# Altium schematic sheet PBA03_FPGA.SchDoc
size D; DocumentNumber: 1; SheetNumber: 1; SheetTotal: 21; PageSetup: Record=PageOptions|CenterHorizontal=True|CenterVertical=True|PrintScale=0.50|XCorrection=1.00|YCorrection=1.00|PrintKind=2|BorderSize=5000000|LeftOffset=0|BottomOffset=0|Orientation=2|PaperLength=1000|PaperWidth=1000|Scale=100|PaperSource=7|PrintQuality=-4|MediaType=1|DitherType=10|PaperKind=A3 (297 x 420mm)|PrintScaleMode=1
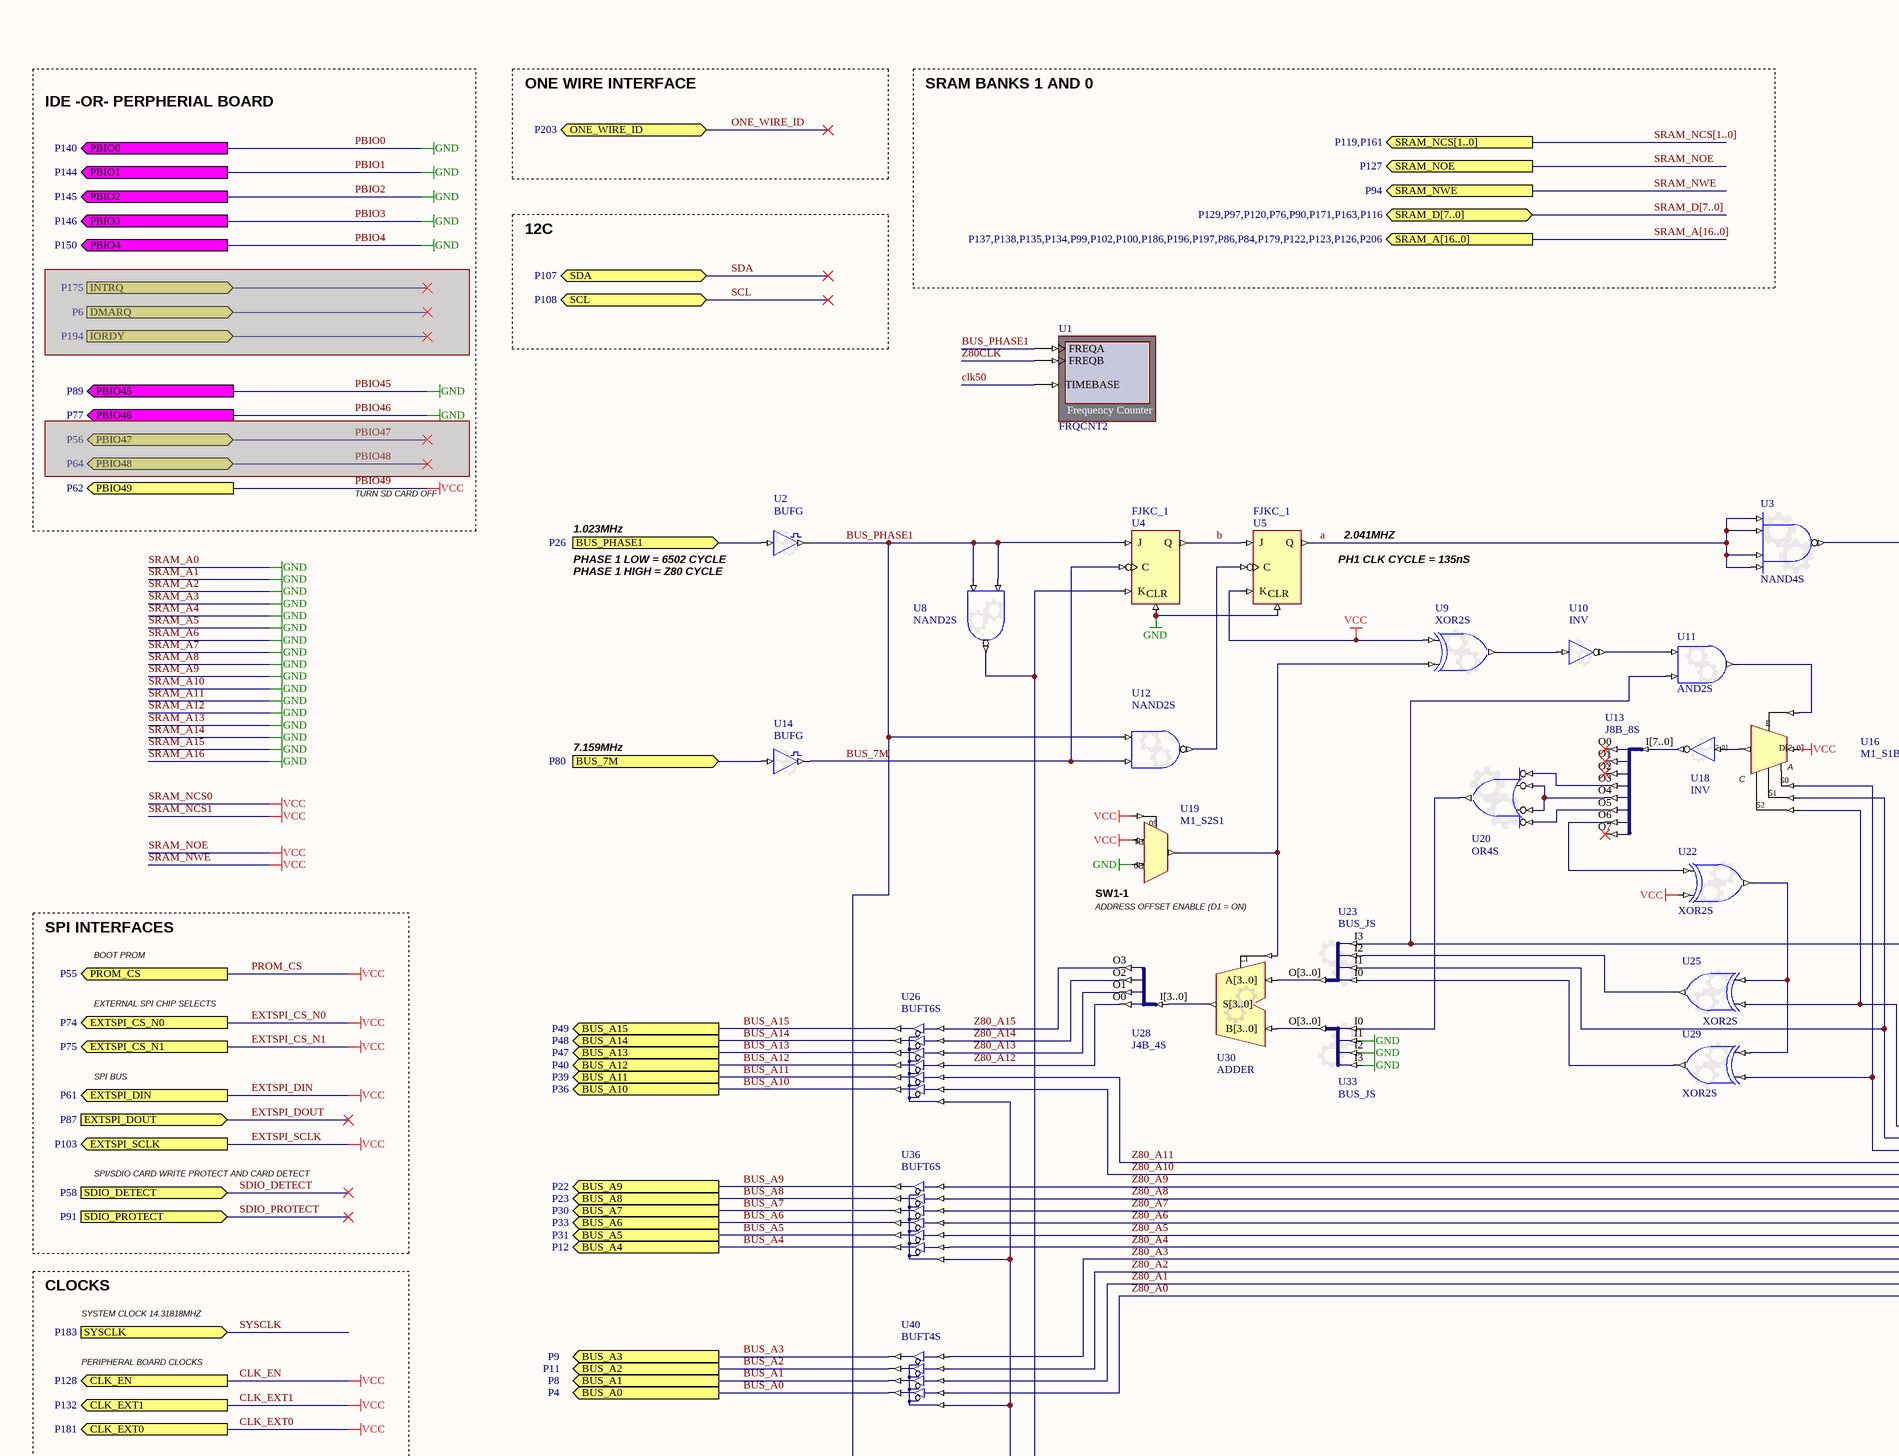
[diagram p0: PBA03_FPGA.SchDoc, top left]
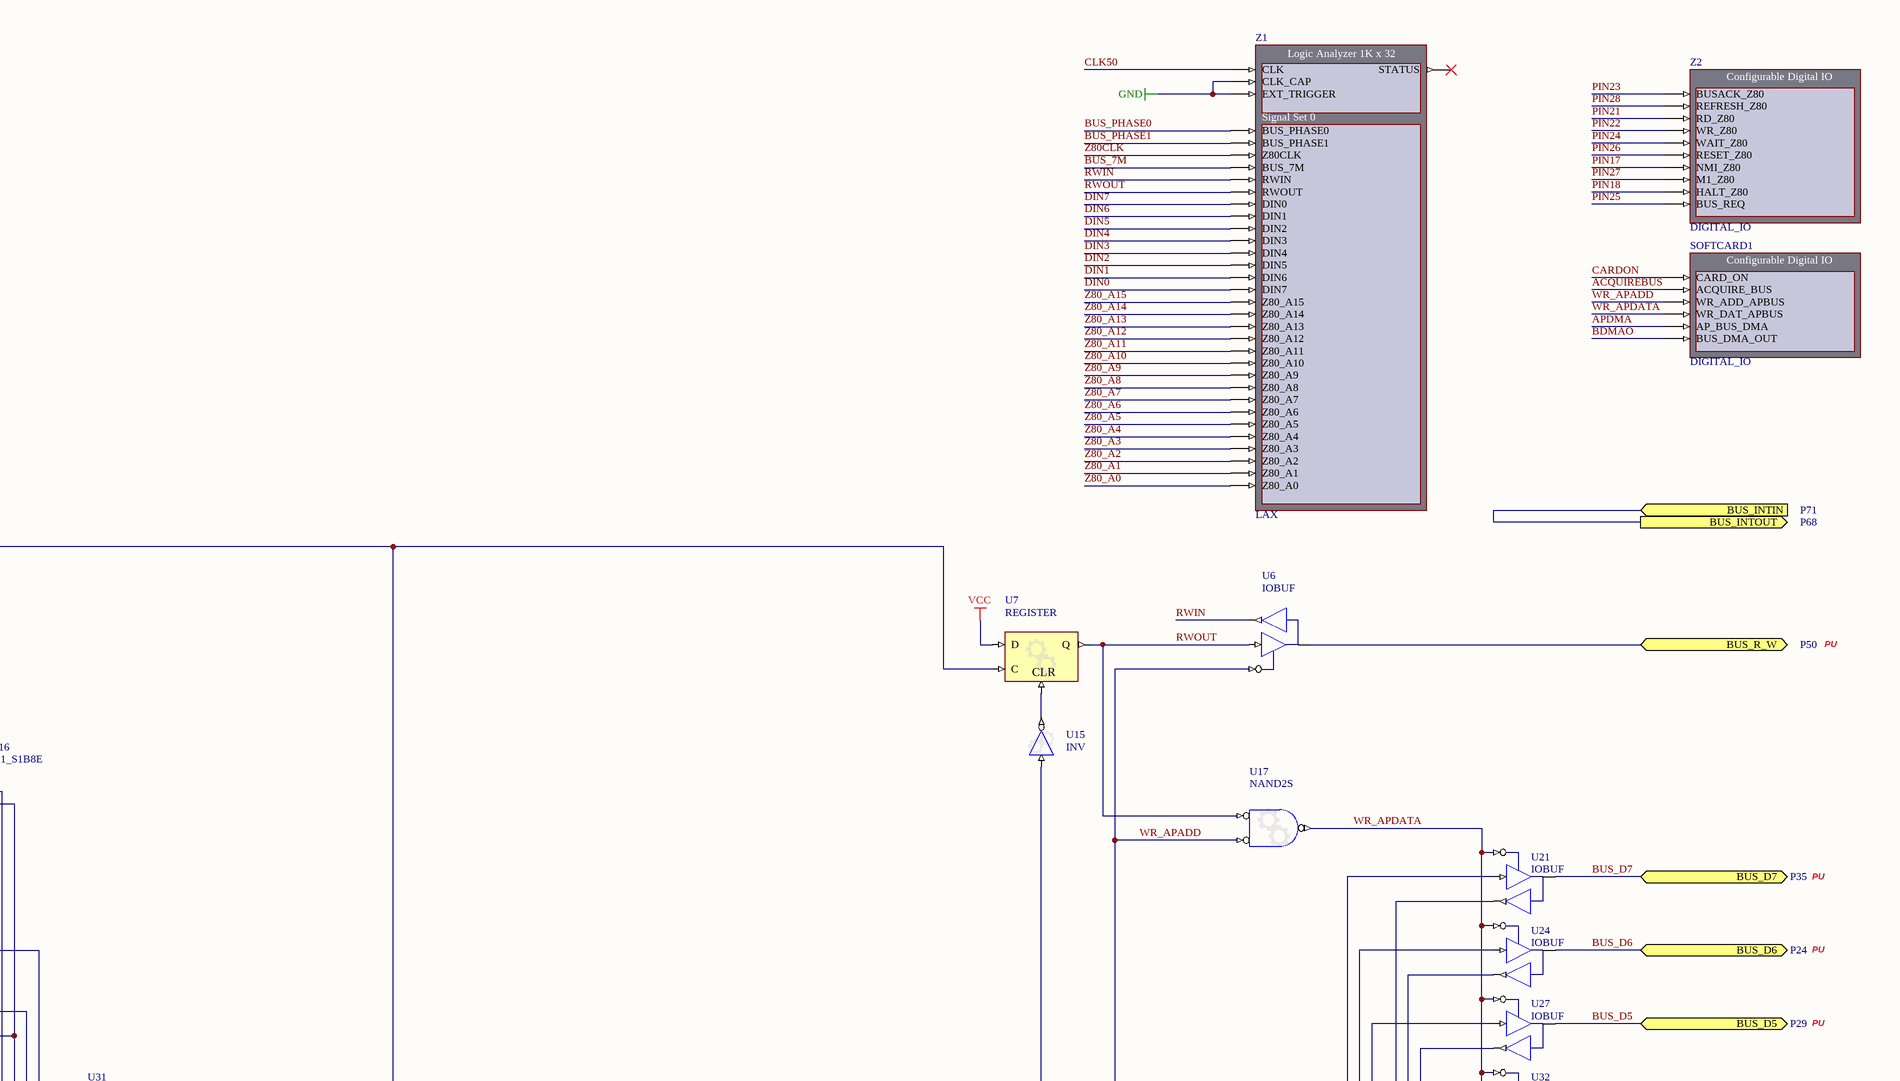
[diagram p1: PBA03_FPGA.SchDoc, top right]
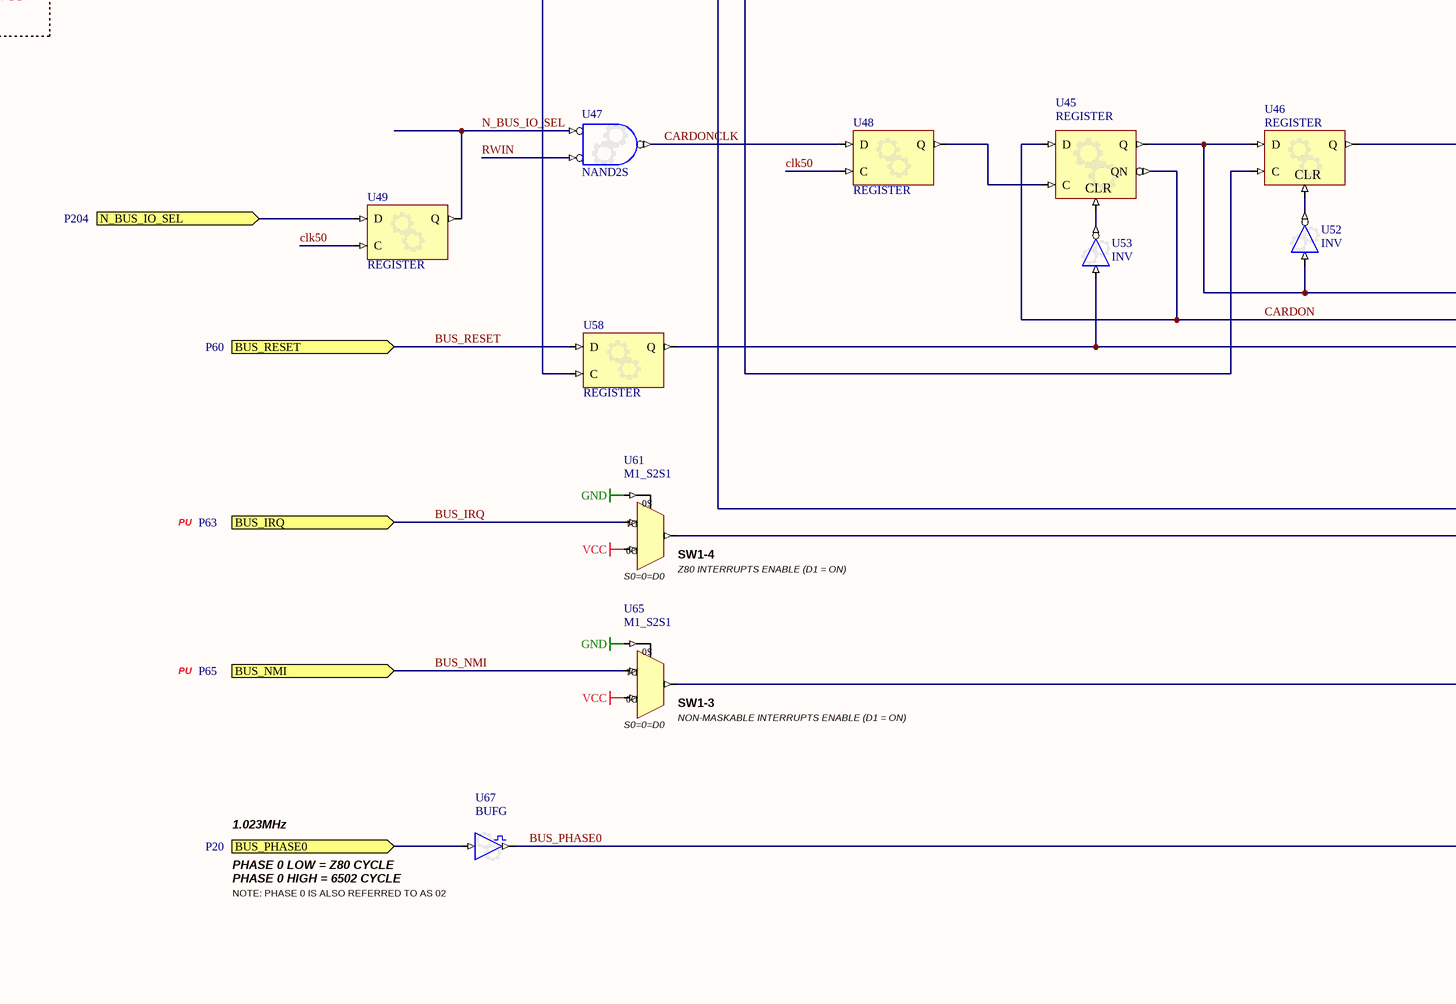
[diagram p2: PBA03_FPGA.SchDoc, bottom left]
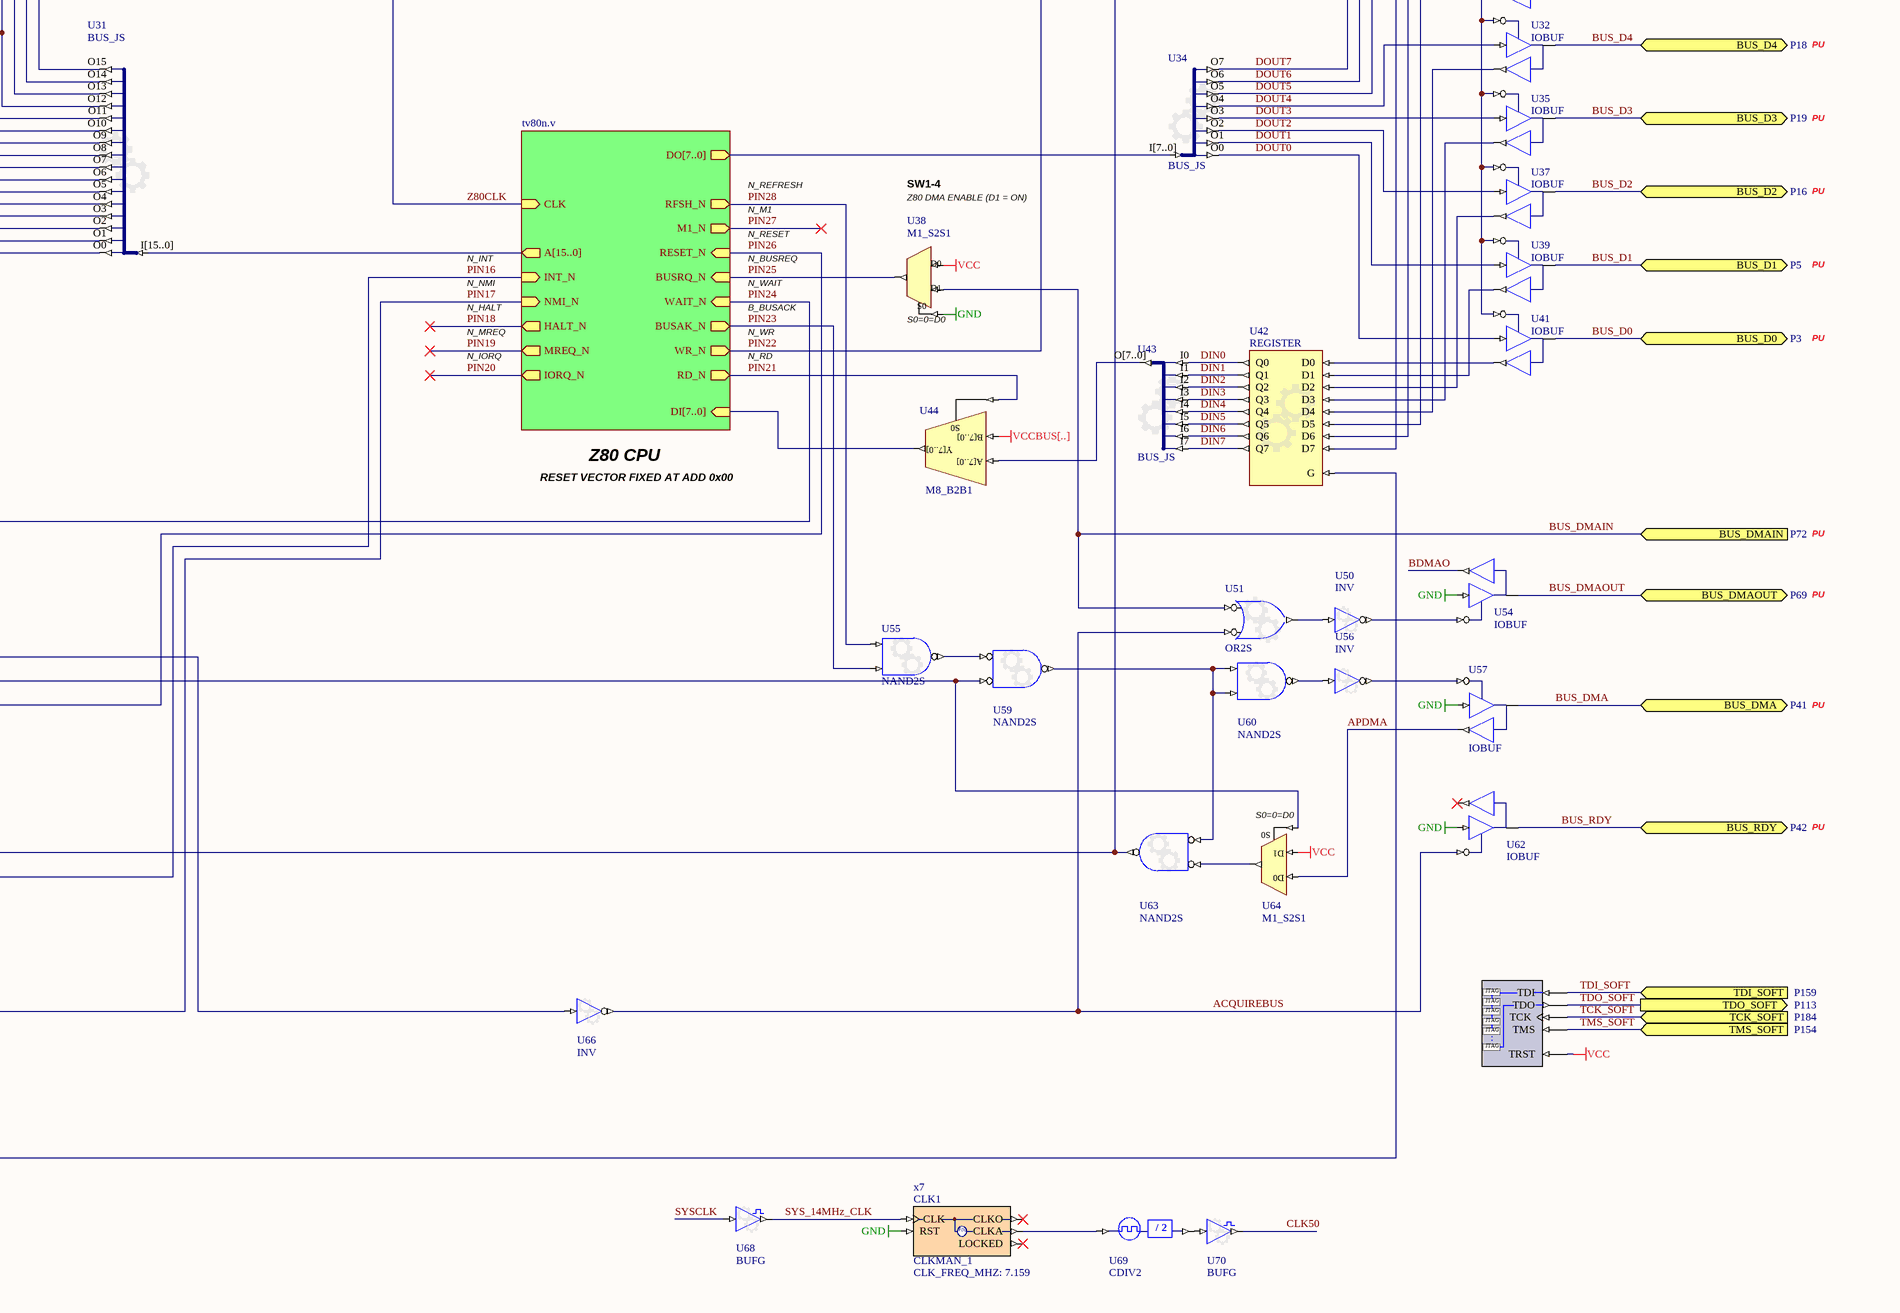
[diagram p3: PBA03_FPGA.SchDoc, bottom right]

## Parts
CLK1  CLKMAN_1  CLK_FREQ_MHZ: 7.159  ClkA_Operation: x7
NEXUS_JTAG_PORT  NEXUS_JTAG_PORT  (value not drawn)
SOFTCARD1  DIGITAL_IO
U1  FRQCNT2
U2  BUFG
U3  NAND4S
U4  FJKC_1
U5  FJKC_1
U6  IOBUF
U7  REGISTER
U8  NAND2S
U9  XOR2S
U10  INV
U11  AND2S
U12  NAND2S
U13  J8B_8S
U14  BUFG
U15  INV
U16  M1_S1B8E
U17  NAND2S
U18  INV
U19  M1_S2S1
U20  OR4S
U21  IOBUF
U22  XOR2S
U23  BUS_JS
U24  IOBUF
U25  XOR2S
U26  BUFT6S
U27  IOBUF
U28  J4B_4S
U29  XOR2S
U30  ADDER
U31  BUS_JS
U32  IOBUF
U33  BUS_JS
U34  BUS_JS
U35  IOBUF
U36  BUFT6S
U37  IOBUF
U38  M1_S2S1
U39  IOBUF
U40  BUFT4S
U41  IOBUF
U42  REGISTER
U43  BUS_JS
U44  M8_B2B1
U45  REGISTER
U46  REGISTER
U47  NAND2S
U48  REGISTER
U49  REGISTER
U50  INV
U51  OR2S
U52  INV
U53  INV
U54  IOBUF
U55  NAND2S
U56  INV
U57  IOBUF
U58  REGISTER
U59  NAND2S
U60  NAND2S
U61  M1_S2S1
U62  IOBUF
U63  NAND2S
U64  M1_S2S1
U65  M1_S2S1
U66  INV
U67  BUFG
U68  BUFG
U69  CDIV2
U70  BUFG
Z1  LAX
Z2  DIGITAL_IO

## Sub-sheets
U_Z80 = tv80n.v: A[15..0] (out), M1_N (out), IORQ_N (out), NMI_N (in), BUSRQ_N (in), RESET_N (in), WAIT_N (in), HALT_N (out), WR_N (out), RFSH_N (out), INT_N (in), BUSAK_N (out), MREQ_N (out), RD_N (out), DO[7..0] (out), DI[7..0] (in), CLK (in)  | : tv80n

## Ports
BUS_7M (in, see P80), BUS_A0 (out, see P4), BUS_A1 (out, see P8), BUS_A2 (out, see P11), BUS_A3 (out, see P9), BUS_A4 (out, see P12), BUS_A5 (out, see P31), BUS_A6 (out, see P33), BUS_A7 (out, see P30), BUS_A8 (out, see P23), BUS_A9 (out, see P22), BUS_A10 (out, see P36), BUS_A11 (out, see P39), BUS_A12 (out, see P40), BUS_A13 (out, see P47), BUS_A14 (out, see P48), BUS_A15 (out, see P49), BUS_D0 (bidir, see P3), BUS_D1 (bidir, see P5), BUS_D2 (bidir, see P16), BUS_D3 (bidir, see P19), BUS_D4 (bidir, see P18), BUS_D5 (bidir, see P29), BUS_D6 (bidir, see P24), BUS_D7 (bidir, see P35), BUS_DMA (bidir, see P41), BUS_DMAIN (in, see P72), BUS_DMAOUT (bidir, see P69), BUS_INTIN (in, see P71), BUS_INTOUT (out, see P68), BUS_IRQ (in, see P63), BUS_NMI (in, see P65), BUS_PHASE0 (in, see P20), BUS_PHASE1 (in, see P26), BUS_R_W (bidir, see P50), BUS_RDY (bidir, see P42), BUS_RESET (in, see P60), CLK_EN (out, see P128), CLK_EXT0 (out, see P181), CLK_EXT1 (out, see P132), DMARQ (in, see P6), EXTSPI_CS_N0 (out, see P74), EXTSPI_CS_N1 (out, see P75), EXTSPI_DIN (out, see P61), EXTSPI_DOUT (in, see P87), EXTSPI_SCLK (out, see P103), INTRQ (in, see P175), IORDY (in, see P194), N_BUS_IO_SEL (in, see P204), ONE_WIRE_ID (bidir, see P203), PBIO0 (out, see P140), PBIO1 (out, see P144), PBIO2 (out, see P145), PBIO3 (out, see P146), PBIO4 (out, see P150), PBIO45 (out, see P89), PBIO46 (out, see P77), PBIO47 (bidir, see P56), PBIO48 (bidir, see P64), PBIO49 (out, see P62), PROM_CS (out, see P55), SCL (bidir, see P108), SDA (bidir, see P107), SDIO_DETECT (in, see P58), SDIO_PROTECT (in, see P91), SRAM_A[16..0] (out, see P137,P138,P135,P134,P99,P102,P100,P186,P196,P197,P86,P84,P179,P122,P123,P126,P206), SRAM_D[7..0] (bidir, see P129,P97,P120,P76,P90,P171,P163,P116), SRAM_NCS[1..0] (out, see P119,P161), SRAM_NOE (out, see P127), SRAM_NWE (out, see P94), SYSCLK (in, see P183), TCK_SOFT (in, see P184), TDI_SOFT (in, see P159), TDO_SOFT (out, see P113), TMS_SOFT (in, see P154)

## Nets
CLK_EN: NEXUS_JTAG_PORT.TRST U5.K U7.D U9.I0 U16.O U19.D1 U19.S0 U22.I0 U38.D0 U61.D0 U64.D1 U65.D0 ; port PROM_CS, port EXTSPI_DIN, port EXTSPI_CS_N0, port EXTSPI_CS_N1, port SRAM_NWE, port EXTSPI_SCLK, port SRAM_NOE, port CLK_EN, port CLK_EXT1, port CLK_EXT0, port PBIO49  [also labelled CLK_EXT0, CLK_EXT1, EXTSPI_CS_N0, EXTSPI_CS_N1, EXTSPI_DIN, EXTSPI_SCLK, PBIO49, PROM_CS, SRAM_NCS0, SRAM_NCS1, SRAM_NOE, SRAM_NWE, VCC]
PBIO0: CLK1.RST U4.CLR U5.CLR U19.D0 U33.I1 U33.I2 U33.I3 U38.S0 U54.I U57.I U61.S0 U62.I U65.S0 Z1.CLK_CAP Z1.EXT_TRIGGER ; port PBIO0, port PBIO1, port PBIO2, port PBIO3, port PBIO4, port PBIO46, port PBIO45  [also labelled GND, PBIO1, PBIO2, PBIO3, PBIO4, PBIO45, PBIO46, SRAM_A0, SRAM_A1, SRAM_A10, SRAM_A11, SRAM_A12, SRAM_A13, SRAM_A14, SRAM_A15, SRAM_A16, SRAM_A2, SRAM_A3, SRAM_A4, SRAM_A5, SRAM_A6, SRAM_A7, SRAM_A8, SRAM_A9]
VCCBUS[..]: U44.B[7..0]
a: U3.I0 U3.I1 U3.I2 U3.I3 U5.Q
ACQUIREBUS: SOFTCARD1.ACQUIRE_BUS U51.I1 U62.T U66.O
APDMA: SOFTCARD1.AP_BUS_DMA U57.O U64.D0
b: U4.Q U5.J
BDMAO: SOFTCARD1.BUS_DMA_OUT U54.O
BUS_7M: U14.I ; port BUS_7M
BUS_7M: U4.C U12.I1 U14.O Z1.BUS_7M  [a separate net that carries the same name]
BUS_A0: U40.O0(Y0) ; port BUS_A0
BUS_A1: U40.O1(Y1) ; port BUS_A1
BUS_A2: U40.O2(Y2) ; port BUS_A2
BUS_A3: U40.O3(Y3) ; port BUS_A3
BUS_A4: U36.O0(Y0) ; port BUS_A4
BUS_A5: U36.O1(Y1) ; port BUS_A5
BUS_A6: U36.O2(Y2) ; port BUS_A6
BUS_A7: U36.O3(Y3) ; port BUS_A7
BUS_A8: U36.O4(Y4) ; port BUS_A8
BUS_A9: U36.O5(Y5) ; port BUS_A9
BUS_A10: U26.O0(Y0) ; port BUS_A10
BUS_A11: U26.O1(Y1) ; port BUS_A11
BUS_A12: U26.O2(Y2) ; port BUS_A12
BUS_A13: U26.O3(Y3) ; port BUS_A13
BUS_A14: U26.O4(Y4) ; port BUS_A14
BUS_A15: U26.O5(Y5) ; port BUS_A15
BUS_D0: U41.IO ; port BUS_D0
BUS_D1: U39.IO ; port BUS_D1
BUS_D2: U37.IO ; port BUS_D2
BUS_D3: U35.IO ; port BUS_D3
BUS_D4: U32.IO ; port BUS_D4
BUS_D5: U27.IO ; port BUS_D5
BUS_D6: U24.IO ; port BUS_D6
BUS_D7: U21.IO ; port BUS_D7
BUS_DMA: U57.IO ; port BUS_DMA
BUS_DMAIN: U38.D1 U51.I0 ; port BUS_DMAIN
BUS_DMAOUT: U54.IO ; port BUS_DMAOUT
BUS_INTIN: port BUS_INTIN, port BUS_INTOUT
BUS_IRQ: U61.D1 ; port BUS_IRQ
BUS_NMI: U65.D1 ; port BUS_NMI
BUS_PHASE0: U42.G U67.O Z1.BUS_PHASE0
BUS_PHASE0: U67.I ; port BUS_PHASE0  [a separate net that carries the same name]
BUS_PHASE1: U2.I ; port BUS_PHASE1
BUS_PHASE1: U1.FREQA U2.O U4.J U8.I0 U8.I1 U12.I0 U58.C Z1.BUS_PHASE1  [a separate net that carries the same name]
BUS_R_W: U6.IO ; port BUS_R_W
BUS_RDY: U62.IO ; port BUS_RDY
BUS_RESET: U58.D ; port BUS_RESET
CARDON: SOFTCARD1.CARD_ON U45.D U45.QN U59.I1 U64.S0
CARDONCLK: U47.O U48.D
CLK50: U1.TIMEBASE U48.C U49.C U70.O Z1.CLK
DIN0: U42.Q0 U43.I0 Z1.DIN7
DIN1: U42.Q1 U43.I1 Z1.DIN6
DIN2: U42.Q2 U43.I2 Z1.DIN5
DIN3: U42.Q3 U43.I3 Z1.DIN4
DIN4: U42.Q4 U43.I4 Z1.DIN3
DIN5: U42.Q5 U43.I5 Z1.DIN2
DIN6: U42.Q6 U43.I6 Z1.DIN1
DIN7: U42.Q7 U43.I7 Z1.DIN0
DOUT0: U34.O0 U41.I
DOUT1: U34.O1 U39.I
DOUT2: U34.O2 U37.I
DOUT3: U34.O3 U35.I
DOUT4: U32.I U34.O4
DOUT5: U27.I U34.O5
DOUT6: U24.I U34.O6
DOUT7: U21.I U34.O7
N_BUS_IO_SEL: U47.I1 U49.Q
N_BUS_IO_SEL: U49.D ; port N_BUS_IO_SEL  [a separate net that carries the same name]
PIN16: U61.O ; sheet U_Z80/INT_N
PIN17: U65.O Z2.NMI_Z80 ; sheet U_Z80/NMI_N
PIN18: Z2.HALT_Z80 ; sheet U_Z80/HALT_N
PIN21: U44.S0 Z2.RD_Z80 ; sheet U_Z80/RD_N
PIN22: U15.I Z2.WR_Z80 ; sheet U_Z80/WR_N
PIN23: U55.I1 Z2.BUSACK_Z80 ; sheet U_Z80/BUSAK_N
PIN24: U46.Q Z2.WAIT_Z80 ; sheet U_Z80/WAIT_N
PIN25: U38.O Z2.BUS_REQ ; sheet U_Z80/BUSRQ_N
PIN26: U53.I U58.Q Z2.RESET_Z80 ; sheet U_Z80/RESET_N
PIN27: Z2.M1_Z80 ; sheet U_Z80/M1_N
PIN28: U55.I0 Z2.REFRESH_Z80 ; sheet U_Z80/RFSH_N
RWIN: U6.O U47.I0 Z1.RWIN
RWOUT: U6.I U7.Q U17.I0 Z1.RWOUT
SYS_14MHz_CLK: CLK1.CLK U68.O
SYSCLK: U68.I ; port SYSCLK
TCK_SOFT: NEXUS_JTAG_PORT.TCK ; port TCK_SOFT
TDI_SOFT: NEXUS_JTAG_PORT.TDI ; port TDI_SOFT
TDO_SOFT: NEXUS_JTAG_PORT.TDO ; port TDO_SOFT
TMS_SOFT: NEXUS_JTAG_PORT.TMS ; port TMS_SOFT
WR_APADD: SOFTCARD1.WR_ADD_APBUS U6.T U17.I1 U26.T U36.T U40.T U63.O
WR_APDATA: SOFTCARD1.WR_DAT_APBUS U17.O U21.T U24.T U27.T U32.T U35.T U37.T U39.T U41.T
Z80_A0: U31.O0 U40.I0 Z1.Z80_A0
Z80_A1: U31.O1 U40.I1 Z1.Z80_A1
Z80_A2: U31.O2 U40.I2 Z1.Z80_A2
Z80_A3: U31.O3 U40.I3 Z1.Z80_A3
Z80_A4: U31.O4 U36.I0 Z1.Z80_A4
Z80_A5: U31.O5 U36.I1 Z1.Z80_A5
Z80_A6: U31.O6 U36.I2 Z1.Z80_A6
Z80_A7: U31.O7 U36.I3 Z1.Z80_A7
Z80_A8: U31.O8 U36.I4 Z1.Z80_A8
Z80_A9: U31.O9 U36.I5 Z1.Z80_A9
Z80_A10: U26.I0 U31.O10 Z1.Z80_A10
Z80_A11: U26.I1 U31.O11 Z1.Z80_A11
Z80_A12: U26.I2 U28.O0 Z1.Z80_A12
Z80_A13: U26.I3 U28.O1 Z1.Z80_A13
Z80_A14: U26.I4 U28.O2 Z1.Z80_A14
Z80_A15: U26.I5 U28.O3 Z1.Z80_A15
Z80CLK: U1.FREQB U3.O U7.C Z1.Z80CLK ; sheet U_Z80/CLK
NetCLK1_CLKA: CLK1.CLKA U69.CLKIN
NetU4_K: U4.K U8.O U46.C
NetU5_C: U5.C U12.O
NetU7_CLR: U7.CLR U15.O
NetU9_I1: U9.I1 U19.O U30.CI
NetU9_O: U9.O U10.I
NetU10_O: U10.O U11.I0
NetU11_I1: U11.I1 U23.I3 U31.O15
NetU11_O: U11.O U16.E
NetU13_O3: U13.O3 U20.I3
NetU13_O4: U13.O4 U20.I1 U20.I2
NetU13_O5: U13.O5 U20.I0
NetU13_O6: U13.O6 U22.I1
NetU16_S0: U16.S0 U29.I1 U31.O12
NetU16_S1: U16.S1 U23.I1 U31.O13
NetU16_S2: U16.S2 U25.I1 U31.O14
NetU20_O: U20.O U33.I0
NetU21_O: U21.O U42.D7
NetU22_O: U22.O U25.I0 U29.I0
NetU23_I0: U23.I0 U29.O
NetU23_I2: U23.I2 U25.O
NetU24_O: U24.O U42.D6
NetU27_O: U27.O U42.D5
NetU32_O: U32.O U42.D4
NetU35_O: U35.O U42.D3
NetU37_O: U37.O U42.D2
NetU39_O: U39.O U42.D1
NetU41_O: U41.O U42.D0
NetU45_C: U45.C U48.Q
NetU45_CLR: U45.CLR U53.O
NetU45_Q: U45.Q U46.D U52.I U66.I
NetU46_CLR: U46.CLR U52.O
NetU50_I: U50.I U51.O
NetU50_O: U50.O U54.T
NetU55_O: U55.O U59.I0
NetU56_I: U56.I U60.O
NetU56_O: U56.O U57.T
NetU59_O: U59.O U60.I0 U60.I1 U63.I1
NetU63_I0: U63.I0 U64.O
NetU69_CLKDV: U69.CLKDV U70.I

Not connected (* = marked no-connect by the designer): CLK1 CLKO* LOCKED*; U13 I[7..0] O0* O1* O2* O7*; U16 D[7..0]; U18 I[7..0] O[7..0]; U23 O[3..0]; U28 I[3..0]; U30 A[3..0] B[3..0] S[3..0]; U31 I[15..0]; U33 O[3..0]; U34 I[7..0]; U43 O[7..0]; U44 A[7..0] Y[7..0]; U62 O*; Z1 STATUS*

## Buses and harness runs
bus SRAM_A[16..0] = port SRAM_A[16..0]
bus SRAM_D[7..0] = port SRAM_D[7..0]
bus SRAM_NCS[1..0] = port SRAM_NCS[1..0]

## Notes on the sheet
- ONE WIRE INTERFACE
- SRAM BANKS 1 AND 0
- IDE -OR- PERPHERIAL BOARD
- 12C
- TURN SD CARD OFF
- 1.023MHz
- PHASE 1 LOW = 6502 CYCLE
- PHASE 1 HIGH = Z80 CYCLE
- (near U5) PH1 CLK CYCLE = 135nS
- (near U5) 2.041MHZ
- PU
- 7.159MHz
- (near U16) C
- (near U16) A
- SPI INTERFACES
- (near U19) SW1-1
- ADDRESS OFFSET ENABLE (D1 = ON)
- BOOT PROM
- EXTERNAL SPI CHIP SELECTS
- SPI BUS
- SPI/SDIO CARD WRITE PROTECT AND CARD DETECT
- N_REFRESH
- SW1-4
- Z80 DMA ENABLE (D1 = ON)
- CLOCKS
- SYSTEM CLOCK 14.31818MHZ
- N_INT
- N_M1
- N_BUSREQ
- N_RESET
- PERIPHERAL BOARD CLOCKS
- N_NMI
- N_HALT
- B_BUSACK
- N_WAIT
- (near U38) S0=0=D0
- N_MREQ
- N_IORQ
- N_RD
- N_WR
- RESET VECTOR FIXED AT ADD 0x00
- Z80 CPU
- (near U64) S0=0=D0
- (near U61) S0=0=D0
- (near U61) SW1-4
- (near U61) Z80 INTERRUPTS ENABLE (D1 = ON)
- (near U65) S0=0=D0
- (near U65) SW1-3
- (near U65) NON-MASKABLE INTERRUPTS ENABLE (D1 = ON)
- PHASE 0 LOW = Z80 CYCLE
- PHASE 0 HIGH = 6502 CYCLE
- NOTE: PHASE 0 IS ALSO REFERRED TO AS 02

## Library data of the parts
CLK1 = CLKMAN_1: Single Operational Output Clock Manager; Clk_Count: 1
NEXUS_JTAG_PORT = NEXUS_JTAG_PORT: Soft Nexus-Chain Connector; NEXUS_JTAG_CONNECTOR: True
SOFTCARD1 = DIGITAL_IO: Configurable Digital IO; NEXUS_CORE: Instrument; NEXUS_JTAG_DEVICE: True; NEXUS_JTAG_ORDER: 0; ConfigurationParameters: {}Version[1.0]{}Input0Name[CARD_ON]{}Input0Width[1]{}Input0InitValue[0]{}Input0Kind[LEDs]{}Input0LEDStyle[Red]{}Input1Name[ACQUIRE_BUS]{}Input1Width[1]{}Input1InitValue[0]{}Input1Kind[LEDs]{}Input1LEDStyle[Red]{}Input2Name[WR_ADD_APBUS]{}Input2Width[1]{}Input2InitValue[0]{}Input2Kind[LEDs]{}Input2LEDStyle[Red]{}Input3Name[WR_DAT_APBUS]{}Input3Width[1]{}Input3InitValue[0]{}Input3Kind[LEDs]{}Input3LEDStyle[Red]{}Input4Name[AP_BUS_DMA]{}Input4Width[1]{}Input4InitValue[0]{}Input4Kind[LEDs]{}Input4LEDStyle[Red]{}Input5Name[BUS_DMA_OUT]{}Input5Width[1]{}Input5InitValue[0]{}Input5Kind[LEDs]{}Input5LEDStyle[Red]{}
U1 = FRQCNT2: Frequency Counter; NEXUS_CORE: Instrument; NEXUS_JTAG_DEVICE: True; NEXUS_JTAG_ORDER: 0
U2 U14 U67 U68 U70 = BUFG: Configurable Global Clock Buffer; ConfiguratorName: GENERIC_BUFFER; ConfigurationParameters: {}Version[1.1]{}SignalCount[1]{}SignalWidth0[1]{}OutputOption0[Global Clock]{}EnableMode[None]{}ShowPinNames[False]{}
U3 = GATE: Configurable Generic Gate; ConfiguratorName: GENERIC_GATE; ConfigurationParameters: {}Version[1.1]{}GateKind[NAND]{}BusInput[False]{}GateInputType[Bit]{}GateOutputOption[Normal]{}BusWidth[8]{}RegisterOutputs[False]{}NegativeClockEdge[False]{}InputCount[4]{}InputInvert0[False]{}InputInvert1[False]{}InputInvert2[False]{}InputInvert3[False]{}
U4 U5 = FJKC_1: J-K Negative Edge Flip-Flop with Asynchronous Clear; SubClass: JK; ClockTrigger: Falling; ArchiveName: GENERIC; VHDLIB_SIM: GENERIC_LIB
U6 U21 U24 U27 U32 U35 U37 U39 U41 U54 U57 U62 = IOBUF: Input/Output Buffer; Enable: Low; Control: Common Control T; ArchiveName: GENERIC; VHDLIB_SIM: GENERIC_LIB
U7 U46 = REGISTER: Configurable Register; ConfiguratorName: GENERIC_REGISTER; ConfigurationParameters: {}Version[1.1]{}RegisterType[DFlipFlop]{}NegativeTrigger[False]{}TriggerEnable[False]{}ResetMode[Asynchronous]{}SetMode[None]{}SignalCount[1]{}SignalWidth0[1]{}OutputOption0[Normal]{}
U8 U12 U55 U60 = GATE: Configurable Generic Gate; ConfiguratorName: GENERIC_GATE; ConfigurationParameters: {}Version[1.1]{}GateKind[NAND]{}BusInput[False]{}GateInputType[Bit]{}GateOutputOption[Normal]{}BusWidth[8]{}RegisterOutputs[False]{}NegativeClockEdge[False]{}InputCount[2]{}InputInvert0[False]{}InputInvert1[False]{}
U9 U22 U25 U29 = GATE: Configurable Generic Gate; ConfiguratorName: GENERIC_GATE; ConfigurationParameters: {}Version[1.1]{}GateKind[XOR]{}BusInput[False]{}GateInputType[Bit]{}GateOutputOption[Normal]{}BusWidth[8]{}RegisterOutputs[False]{}NegativeClockEdge[False]{}InputCount[2]{}InputInvert0[False]{}InputInvert1[False]{}
U10 U15 U50 U52 U53 U56 U66 = INV: Configurable Inverter; ConfiguratorName: GENERIC_BUFFER; ConfigurationParameters: {}Version[1.1]{}SignalCount[1]{}SignalWidth0[1]{}OutputOption0[Inverted]{}EnableMode[None]{}ShowPinNames[False]{}
U11 = GATE: Configurable Generic Gate; ConfiguratorName: GENERIC_GATE; ConfigurationParameters: {}Version[1.1]{}GateKind[AND]{}BusInput[False]{}GateInputType[Bit]{}GateOutputOption[Normal]{}BusWidth[8]{}RegisterOutputs[False]{}NegativeClockEdge[False]{}InputCount[2]{}InputInvert0[False]{}InputInvert1[False]{}
U13 = J8B_8S: 8-Bit input bus to 8 single pin outputs; FunctionalClass: Bus Joiner; PortSize: 8; ArchiveName: GENERIC; VHDLIB_SIM: GENERIC_LIB
U16 = M1_S1B8E: 1x1-Single Wire to 1x8-Bit Bus Multiplexer (Demultiplex) With Enable; SubClass: S1Bn; Enable: High; PortSize: 1; PortStyle: Bus Version; ArchiveName: GENERIC; VHDLIB_SIM: GENERIC_LIB
U17 U47 U59 U63 = GATE: Configurable Generic Gate; ConfiguratorName: GENERIC_GATE; ConfigurationParameters: {}Version[1.1]{}GateKind[NAND]{}BusInput[False]{}GateInputType[Bit]{}GateOutputOption[Normal]{}BusWidth[8]{}RegisterOutputs[False]{}NegativeClockEdge[False]{}InputCount[2]{}InputInvert0[True]{}InputInvert1[True]{}
U18 = INV: Configurable Inverter; ConfigurationParameters: {}Version[1.1]{}SignalCount[1]{}SignalWidth0[8]{}OutputOption0[Inverted]{}EnableMode[None]{}ShowPinNames[False]{}; ConfiguratorName: GENERIC_BUFFER
U19 U38 U61 U64 U65 = M1_S2S1: 2x1-Single Wire to 1x1-Single Wire Multiplexer; XilinxEquivalent: M2_1; SubClass: SnS1; PortSize: 1; PortStyle: Single Pin Version; ArchiveName: GENERIC; VHDLIB_SIM: GENERIC_LIB
U20 = GATE: Configurable Generic Gate; ConfiguratorName: GENERIC_GATE; ConfigurationParameters: {}Version[1.1]{}GateKind[OR]{}BusInput[False]{}GateInputType[Bit]{}GateOutputOption[Normal]{}BusWidth[8]{}RegisterOutputs[False]{}NegativeClockEdge[False]{}InputCount[4]{}InputInvert0[True]{}InputInvert1[True]{}InputInvert2[True]{}InputInvert3[True]{}
U23 U33 = BUS_JS: Configurable Bus Joiner/Splitter; ConfiguratorName: GENERIC_BUS_JS; ConfigurationParameters: {}Version[1.1]{}SplitterJoinerType[Joiner]{}SignalCount[4]{}SignalWidth0[1]{}GapBelow0[1000000]{}ConnectionType0[Pin]{}SignalWidth1[1]{}GapBelow1[1000000]{}ConnectionType1[Pin]{}SignalWidth2[1]{}GapBelow2[1000000]{}ConnectionType2[Pin]{}SignalWidth3[1]{}GapBelow3[1000000]{}ConnectionType3[Pin]{}ShowPinNames[True]{}
U26 U36 = BUFT6S: 6-Bit 3-state Buffer with Active Low Enable, Single Pin Version; SubClass: BUFT; PortSize: 6; ArchiveName: GENERIC; VHDLIB_SIM: GENERIC_LIB
U28 = J4B_4S: 4-Bit input bus to 4 Single pin outputs; FunctionalClass: Bus Joiner; PortSize: 4; ArchiveName: GENERIC; VHDLIB_SIM: GENERIC_LIB
U30 = ADDER: Configurable Adder; ConfiguratorName: GENERIC_ADDER; ConfigurationParameters: {}Version[1.0]{}Type[Adder]{}SignedOverflow[False]{}UnsignedCarryOut[False]{}SignalWidth[4]{}BusInputs[True]{}BusOutput[True]{}RegisterOutputs[False]{}NegClockEdge[False]{}CarryIn[True]{}
U31 = BUS_JS: Configurable Bus Joiner/Splitter; ConfiguratorName: GENERIC_BUS_JS; ConfigurationParameters: {}Version[1.1]{}SplitterJoinerType[Splitter]{}SignalCount[16]{}SignalWidth0[1]{}GapBelow0[1000000]{}ConnectionType0[Pin]{}SignalWidth1[1]{}GapBelow1[1000000]{}ConnectionType1[Pin]{}SignalWidth2[1]{}GapBelow2[1000000]{}ConnectionType2[Pin]{}SignalWidth3[1]{}GapBelow3[1000000]{}ConnectionType3[Pin]{}SignalWidth4[1]{}GapBelow4[1000000]{}ConnectionType4[Pin]{}SignalWidth5[1]{}GapBelow5[1000000]{}ConnectionType5[Pin]{}SignalWidth6[1]{}GapBelow6[1000000]{}ConnectionType6[Pin]{}SignalWidth7[1]{}GapBelow7[1000000]{}ConnectionType7[Pin]{}SignalWidth8[1]{}GapBelow8[1000000]{}ConnectionType8[Pin]{}SignalWidth9[1]{}GapBelow9[1000000]{}ConnectionType9[Pin]{}SignalWidth10[1]{}GapBelow10[1000000]{}ConnectionType10[Pin]{}SignalWidth11[1]{}GapBelow11[1000000]{}ConnectionType11[Pin]{}SignalWidth12[1]{}GapBelow12[1000000]{}ConnectionType12[Pin]{}SignalWidth13[1]{}GapBelow13[1000000]{}ConnectionType13[Pin]{}SignalWidth14[1]{}GapBelow14[1000000]{}ConnectionType14[Pin]{}SignalWidth15[1]{}GapBelow15[1000000]{}ConnectionType15[Pin]{}ShowPinNames[True]{}
U34 = BUS_JS: Configurable Bus Joiner/Splitter; ConfiguratorName: GENERIC_BUS_JS; ConfigurationParameters: {}Version[1.1]{}SplitterJoinerType[Splitter]{}SignalCount[8]{}SignalWidth0[1]{}GapBelow0[1000000]{}ConnectionType0[Pin]{}SignalWidth1[1]{}GapBelow1[1000000]{}ConnectionType1[Pin]{}SignalWidth2[1]{}GapBelow2[1000000]{}ConnectionType2[Pin]{}SignalWidth3[1]{}GapBelow3[1000000]{}ConnectionType3[Pin]{}SignalWidth4[1]{}GapBelow4[1000000]{}ConnectionType4[Pin]{}SignalWidth5[1]{}GapBelow5[1000000]{}ConnectionType5[Pin]{}SignalWidth6[1]{}GapBelow6[1000000]{}ConnectionType6[Pin]{}SignalWidth7[1]{}GapBelow7[1000000]{}ConnectionType7[Pin]{}ShowPinNames[True]{}
U40 = BUFT4S: 4-Bit 3-state Buffer with Active Low Enable, Single Pin Version; XilinxEquivalent: BUFT4; SubClass: BUFT; PortSize: 4; ArchiveName: GENERIC; VHDLIB_SIM: GENERIC_LIB
U42 = REGISTER: Configurable Register; ConfiguratorName: GENERIC_REGISTER; ConfigurationParameters: {}Version[1.1]{}RegisterType[TransparentLatch]{}NegativeTrigger[False]{}TriggerEnable[False]{}ResetMode[None]{}SetMode[None]{}SignalCount[8]{}SignalWidth0[1]{}OutputOption0[Normal]{}SignalWidth1[1]{}OutputOption1[Normal]{}SignalWidth2[1]{}OutputOption2[Normal]{}SignalWidth3[1]{}OutputOption3[Normal]{}SignalWidth4[1]{}OutputOption4[Normal]{}SignalWidth5[1]{}OutputOption5[Normal]{}SignalWidth6[1]{}OutputOption6[Normal]{}SignalWidth7[1]{}OutputOption7[Normal]{}
U43 = BUS_JS: Configurable Bus Joiner/Splitter; ConfiguratorName: GENERIC_BUS_JS; ConfigurationParameters: {}Version[1.1]{}SplitterJoinerType[Joiner]{}SignalCount[8]{}SignalWidth0[1]{}GapBelow0[1000000]{}ConnectionType0[Pin]{}SignalWidth1[1]{}GapBelow1[1000000]{}ConnectionType1[Pin]{}SignalWidth2[1]{}GapBelow2[1000000]{}ConnectionType2[Pin]{}SignalWidth3[1]{}GapBelow3[1000000]{}ConnectionType3[Pin]{}SignalWidth4[1]{}GapBelow4[1000000]{}ConnectionType4[Pin]{}SignalWidth5[1]{}GapBelow5[1000000]{}ConnectionType5[Pin]{}SignalWidth6[1]{}GapBelow6[1000000]{}ConnectionType6[Pin]{}SignalWidth7[1]{}GapBelow7[1000000]{}ConnectionType7[Pin]{}ShowPinNames[True]{}
U44 = M8_B2B1: 2x8-Bit Bus to 1x8-Bit Bus Multiplexer; SubClass: BnB1; PortSize: 8; PortStyle: Bus Version; ArchiveName: GENERIC; VHDLIB_SIM: GENERIC_LIB
U45 = REGISTER: Configurable Register; ConfiguratorName: GENERIC_REGISTER; ConfigurationParameters: {}Version[1.1]{}RegisterType[DFlipFlop]{}NegativeTrigger[False]{}TriggerEnable[False]{}ResetMode[Asynchronous]{}SetMode[None]{}SignalCount[1]{}SignalWidth0[1]{}OutputOption0[Both]{}
U48 U49 U58 = REGISTER: Configurable Register; ConfiguratorName: GENERIC_REGISTER; ConfigurationParameters: {}Version[1.1]{}RegisterType[DFlipFlop]{}NegativeTrigger[False]{}TriggerEnable[False]{}ResetMode[None]{}SetMode[None]{}SignalCount[1]{}SignalWidth0[1]{}OutputOption0[Normal]{}
U51 = GATE: Configurable Generic Gate; ConfiguratorName: GENERIC_GATE; ConfigurationParameters: {}Version[1.1]{}GateKind[OR]{}BusInput[False]{}GateInputType[Bit]{}GateOutputOption[Normal]{}BusWidth[8]{}RegisterOutputs[False]{}NegativeClockEdge[False]{}InputCount[2]{}InputInvert0[True]{}InputInvert1[True]{}
U69 = CDIV2: Clock Divider by 2; DivisorRate: 2; ArchiveName: GENERIC; VHDLIB_SIM: GENERIC_LIB
Z1 = LAX: Configurable Logic Analyzer; NEXUS_CORE: Instrument; NEXUS_JTAG_DEVICE: True; NEXUS_JTAG_ORDER: 0; ConfiguratorName: LogicAnalyser; ConfigurationParameters: {}Version[1.0]{}CaptureWidth[32]{}MemorySize[1K]{}ExtAddrWidth[10]{}Set0[Signal Set 0]{}Set0_Signal0[BUS_PHASE0]{}Style_Set0_Signal0[Default]{}Set0_Signal1[BUS_PHASE1]{}Style_Set0_Signal1[Default]{}Set0_Signal2[Z80CLK]{}Style_Set0_Signal2[Default]{}Set0_Signal3[BUS_7M]{}Style_Set0_Signal3[Default]{}Set0_Signal4[RWIN]{}Style_Set0_Signal4[Default]{}Set0_Signal5[RWOUT]{}Style_Set0_Signal5[Default]{}Set0_Signal6[DIN0]{}Style_Set0_Signal6[Default]{}Set0_Signal7[DIN1]{}Style_Set0_Signal7[Default]{}Set0_Signal8[DIN2]{}Style_Set0_Signal8[Default]{}Set0_Signal9[DIN3]{}Style_Set0_Signal9[Default]{}Set0_Signal10[DIN4]{}Style_Set0_Signal10[Default]{}Set0_Signal11[DIN5]{}Style_Set0_Signal11[Default]{}Set0_Signal12[DIN6]{}Style_Set0_Signal12[Default]{}Set0_Signal13[DIN7]{}Style_Set0_Signal13[Default]{}Set0_Signal14[Z80_A15]{}Style_Set0_Signal14[Default]{}Set0_Signal15[Z80_A14]{}Style_Set0_Signal15[Default]{}Set0_Signal16[Z80_A13]{}Style_Set0_Signal16[Default]{}Set0_Signal17[Z80_A12]{}Style_Set0_Signal17[Default]{}Set0_Signal18[Z80_A11]{}Style_Set0_Signal18[Default]{}Set0_Signal19[Z80_A10]{}Style_Set0_Signal19[Default]{}Set0_Signal20[Z80_A9]{}Style_Set0_Signal20[Default]{}Set0_Signal21[Z80_A8]{}Style_Set0_Signal21[Default]{}Set0_Signal22[Z80_A7]{}Style_Set0_Signal22[Default]{}Set0_Signal23[Z80_A6]{}Style_Set0_Signal23[Default]{}Set0_Signal24[Z80_A5]{}Style_Set0_Signal24[Default]{}Set0_Signal25[Z80_A4]{}Style_Set0_Signal25[Default]{}Set0_Signal26[Z80_A3]{}Style_Set0_Signal26[Default]{}Set0_Signal27[Z80_A2]{}Style_Set0_Signal27[Default]{}Set0_Signal28[Z80_A1]{}Style_Set0_Signal28[Default]{}Set0_Signal29[Z80_A0]{}Style_Set0_Signal29[Default]{}; ChildModel1: LAX_CFG32
Z2 = DIGITAL_IO: Configurable Digital IO; NEXUS_CORE: Instrument; NEXUS_JTAG_DEVICE: True; NEXUS_JTAG_ORDER: 0; ConfigurationParameters: {}Version[1.0]{}Input0Name[BUSACK_Z80]{}Input0Width[1]{}Input0InitValue[0]{}Input0Kind[LEDs]{}Input0LEDStyle[Red]{}Input1Name[REFRESH_Z80]{}Input1Width[1]{}Input1InitValue[0]{}Input1Kind[LEDs]{}Input1LEDStyle[Red]{}Input2Name[RD_Z80]{}Input2Width[1]{}Input2InitValue[0]{}Input2Kind[LEDs]{}Input2LEDStyle[Red]{}Input3Name[WR_Z80]{}Input3Width[1]{}Input3InitValue[0]{}Input3Kind[LEDs]{}Input3LEDStyle[Red]{}Input4Name[WAIT_Z80]{}Input4Width[1]{}Input4InitValue[0]{}Input4Kind[LEDs]{}Input4LEDStyle[Red]{}Input5Name[RESET_Z80]{}Input5Width[1]{}Input5InitValue[0]{}Input5Kind[LEDs]{}Input5LEDStyle[Red]{}Input6Name[NMI_Z80]{}Input6Width[1]{}Input6InitValue[0]{}Input6Kind[LEDs]{}Input6LEDStyle[Red]{}Input7Name[M1_Z80]{}Input7Width[1]{}Input7InitValue[0]{}Input7Kind[LEDs]{}Input7LEDStyle[Red]{}Input8Name[HALT_Z80]{}Input8Width[1]{}Input8InitValue[0]{}Input8Kind[LEDs]{}Input8LEDStyle[Red]{}Input9Name[BUS_REQ]{}Input9Width[1]{}Input9InitValue[0]{}Input9Kind[LEDs]{}Input9LEDStyle[Red]{}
